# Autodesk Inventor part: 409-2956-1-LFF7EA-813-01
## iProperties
Created: 2010-11
Part Number: 409-2956-1-LFF7EA-813-01
Material: 3/8" OD TUBE - SS
Description: PT TUBING
Document SubType Name: Modeling
Designer: S. Boerckel
Engineer: Steve Boerckel
Mass: 769.029 g
Surface Area: 1665.99 cm^2
Volume: 95.1769 cm^3
Density: 8.08 g/cm^3
Author: S. Boerckel
Revision Number: 0
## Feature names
1. Sweep1
